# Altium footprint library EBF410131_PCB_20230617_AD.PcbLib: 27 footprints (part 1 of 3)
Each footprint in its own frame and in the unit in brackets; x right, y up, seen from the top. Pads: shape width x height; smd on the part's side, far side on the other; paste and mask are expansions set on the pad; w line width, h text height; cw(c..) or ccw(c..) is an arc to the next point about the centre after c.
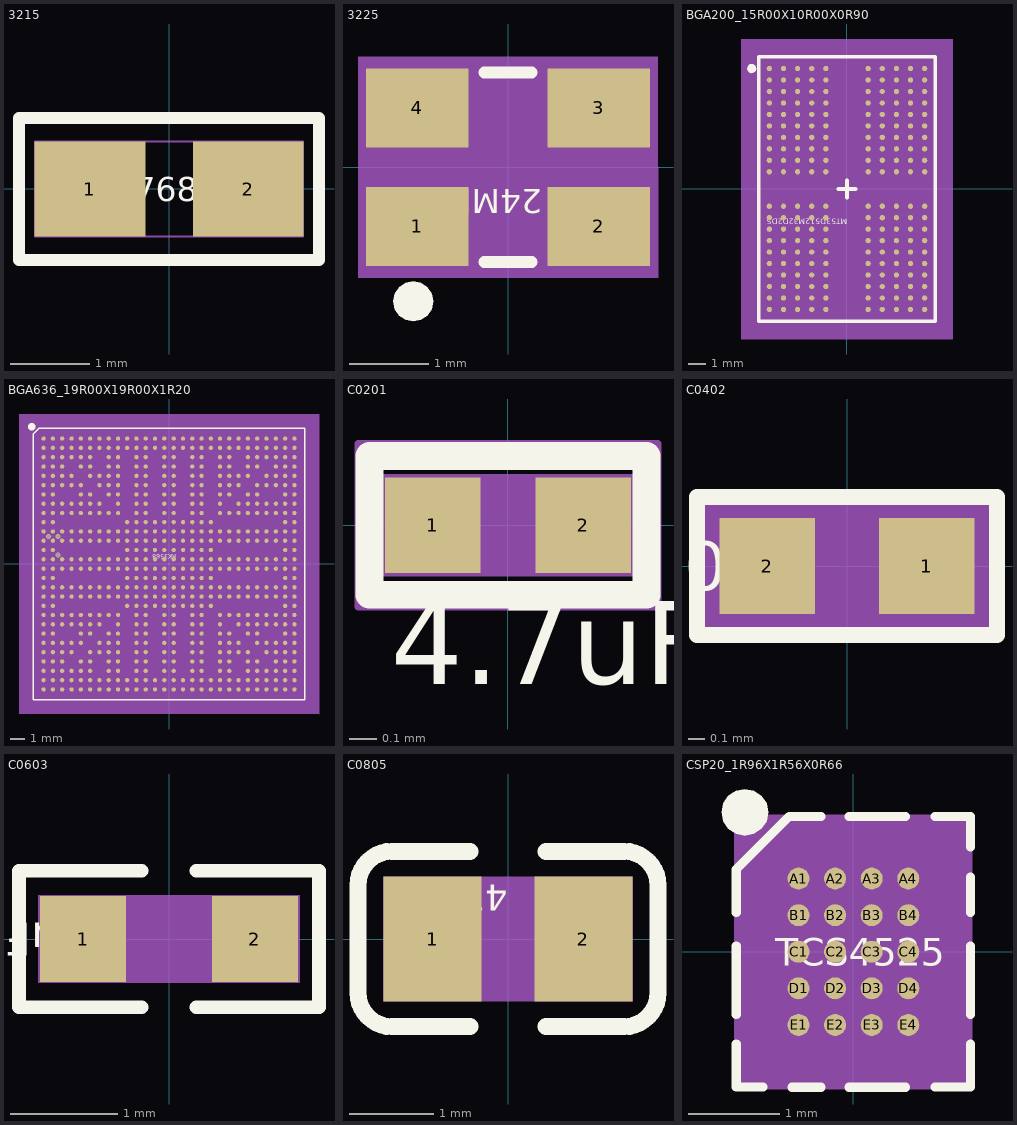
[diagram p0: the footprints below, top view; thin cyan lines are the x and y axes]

## 3215 [mm] "3215"
pads (2):
  rect 1.4x1.2 smd: 1(-1.001,0) 2(1.001,0)
Top Overlay:
  lines w0.15: -1.9,-0.899 -1.9,0.899 1.9,0.899 1.9,-0.899 -1.9,-0.899
  text "32.768KHz" at -1.097,-0.152 h0.3
Top 3D Body:
  lines w0.025: -1.699,-0.599 1.699,-0.599 1.699,0.599 -1.699,0.599 -1.699,-0.599
Mechanical 12:
  text "1" at -1.153,0 h0.38
  text "2" at 0.848,0 h0.38

## 3225 [mm] "3225"
pads (4):
  rect 1.3x1 smd: 1(-1.15,-0.75) 2(1.15,-0.75) 3(1.15,0.75) 4(-1.15,0.75)
Top Overlay:
  dashed: -1.38,-1.52 -1.436,-1.602 -1.455,-1.7 -1.436,-1.798 -1.38,-1.88 -1.298,-1.936 -1.265,-1.942 -1.2,-1.955 -1.102,-1.936 -1.02,-1.88 -0.965,-1.798 -0.945,-1.7 -0.958,-1.635 -0.965,-1.602 -1.02,-1.52 -1.102,-1.464 -1.2,-1.445 -1.298,-1.464
  lines w0.15: -0.3,-1.2 0.3,-1.2 ; -0.3,1.2 0.3,1.2
  text "24MHz" at 0.431,-0.279 h0.3
Top 3D Body:
  region: -1.9,1.4 -1.9,-1.4 1.9,-1.4 1.9,1.4
Mechanical 12:
  text "2" at 1.401,-1.001 h0.89
  text "4" at -0.899,0.499 h0.89
  text "1" at -0.899,-1.001 h0.89
  text "3" at 1.401,0.499 h0.89
Top Assembly:
  lines w0.15: -1.6,-1.25 1.6,-1.25 1.6,1.25 -1.6,1.25 -1.6,-1.25
3D body: height 3.81, standoff 0, extent -1.9,-1.4 1.9,1.4

## BGA200_15R00X10R00X0R90 [mm] "BGA200_15R00X10R00X0R90"
pads (200):
  round 0.3 smd: A1(-4.4,6.825) A2(-3.6,6.825) A3(-2.8,6.825) A4(-2,6.825) A5(-1.2,6.825) A8(1.2,6.825) A9(2,6.825) A10(2.8,6.825) A11(3.6,6.825) A12(4.4,6.825) AA1(-4.4,-6.175) AA2(-3.6,-6.175) AA3(-2.8,-6.175) AA4(-2,-6.175) AA5(-1.2,-6.175) AA8(1.2,-6.175) AA9(2,-6.175) AA10(2.8,-6.175) AA11(3.6,-6.175) AA12(4.4,-6.175) AB1(-4.4,-6.825) AB2(-3.6,-6.825) AB3(-2.8,-6.825) AB4(-2,-6.825) AB5(-1.2,-6.825) AB8(1.2,-6.825) AB9(2,-6.825) AB10(2.8,-6.825) AB11(3.6,-6.825) AB12(4.4,-6.825) B1(-4.4,6.175) B2(-3.6,6.175) B3(-2.8,6.175) B4(-2,6.175) B5(-1.2,6.175) B8(1.2,6.175) B9(2,6.175) B10(2.8,6.175) B11(3.6,6.175) B12(4.4,6.175) C1(-4.4,5.525) C2(-3.6,5.525) C3(-2.8,5.525) C4(-2,5.525) C5(-1.2,5.525) C8(1.2,5.525) C9(2,5.525) C10(2.8,5.525) C11(3.6,5.525) C12(4.4,5.525) D1(-4.4,4.875) D2(-3.6,4.875) D3(-2.8,4.875) D4(-2,4.875) D5(-1.2,4.875) D8(1.2,4.875) D9(2,4.875) D10(2.8,4.875) D11(3.6,4.875) D12(4.4,4.875) E1(-4.4,4.225) E2(-3.6,4.225) E3(-2.8,4.225) E4(-2,4.225) E5(-1.2,4.225) E8(1.2,4.225) E9(2,4.225) E10(2.8,4.225) E11(3.6,4.225) E12(4.4,4.225) F1(-4.4,3.575) F2(-3.6,3.575) F3(-2.8,3.575) F4(-2,3.575) F5(-1.2,3.575) F8(1.2,3.575) F9(2,3.575) F10(2.8,3.575) F11(3.6,3.575) F12(4.4,3.575) G1(-4.4,2.925) G2(-3.6,2.925) G3(-2.8,2.925) G4(-2,2.925) G5(-1.2,2.925) G8(1.2,2.925) G9(2,2.925) G10(2.8,2.925) G11(3.6,2.925) G12(4.4,2.925) H1(-4.4,2.275) H2(-3.6,2.275) H3(-2.8,2.275) H4(-2,2.275) H5(-1.2,2.275) H8(1.2,2.275) H9(2,2.275) H10(2.8,2.275) H11(3.6,2.275) H12(4.4,2.275) J1(-4.4,1.625) J2(-3.6,1.625) J3(-2.8,1.625) J4(-2,1.625) J5(-1.2,1.625) J8(1.2,1.625) J9(2,1.625) J10(2.8,1.625) J11(3.6,1.625) J12(4.4,1.625) K1(-4.4,0.975) K2(-3.6,0.975) K3(-2.8,0.975) K4(-2,0.975) K5(-1.2,0.975) K8(1.2,0.975) K9(2,0.975) K10(2.8,0.975) K11(3.6,0.975) K12(4.4,0.975) N1(-4.4,-0.975) N2(-3.6,-0.975) N3(-2.8,-0.975) N4(-2,-0.975) N5(-1.2,-0.975) N8(1.2,-0.975) N9(2,-0.975) N10(2.8,-0.975) N11(3.6,-0.975) N12(4.4,-0.975) P1(-4.4,-1.625) P2(-3.6,-1.625) P3(-2.8,-1.625) P4(-2,-1.625) P5(-1.2,-1.625) P8(1.2,-1.625) P9(2,-1.625) P10(2.8,-1.625) P11(3.6,-1.625) P12(4.4,-1.625) R1(-4.4,-2.275) R2(-3.6,-2.275) R3(-2.8,-2.275) R4(-2,-2.275) R5(-1.2,-2.275) R8(1.2,-2.275) R9(2,-2.275) R10(2.8,-2.275) R11(3.6,-2.275) R12(4.4,-2.275) T1(-4.4,-2.925) T2(-3.6,-2.925) T3(-2.8,-2.925) T4(-2,-2.925) T5(-1.2,-2.925) T8(1.2,-2.925) T9(2,-2.925) T10(2.8,-2.925) T11(3.6,-2.925) T12(4.4,-2.925) U1(-4.4,-3.575) U2(-3.6,-3.575) U3(-2.8,-3.575) U4(-2,-3.575) U5(-1.2,-3.575) U8(1.2,-3.575) U9(2,-3.575) U10(2.8,-3.575) U11(3.6,-3.575) U12(4.4,-3.575) V1(-4.4,-4.225) V2(-3.6,-4.225) V3(-2.8,-4.225) V4(-2,-4.225) V5(-1.2,-4.225) V8(1.2,-4.225) V9(2,-4.225) V10(2.8,-4.225) V11(3.6,-4.225) V12(4.4,-4.225) W1(-4.4,-4.875) W2(-3.6,-4.875) W3(-2.8,-4.875) W4(-2,-4.875) W5(-1.2,-4.875) W8(1.2,-4.875) W9(2,-4.875) W10(2.8,-4.875) W11(3.6,-4.875) W12(4.4,-4.875) Y1(-4.4,-5.525) Y2(-3.6,-5.525) Y3(-2.8,-5.525) Y4(-2,-5.525) Y5(-1.2,-5.525) Y8(1.2,-5.525) Y9(2,-5.525) Y10(2.8,-5.525) Y11(3.6,-5.525) Y12(4.4,-5.525)
Top Overlay:
  dashed: -5.4,7.08 -5.498,7.06 -5.58,7.005 -5.635,6.923 -5.655,6.825 -5.635,6.727 -5.617,6.7 -5.58,6.645 -5.498,6.589 -5.4,6.57 -5.302,6.589 -5.22,6.645 -5.183,6.7 -5.164,6.727 -5.145,6.825 -5.164,6.923 -5.22,7.005 -5.302,7.06
  lines w0.2: -0.5,0 0,0 ; 0,-0.5 0,0 ; 0,0.5 0,0 ; 0.5,0 0,0 ; -5,-7.5 -5,7.5 5,7.5 5,-7.5 -5,-7.5
  text "MT53D512M32D2DS" at 0,-1.676 h0.3
Top 3D Body:
  region: -6,-8.5 -6,8.5 6,8.5 6,-8.5
Mechanical 12:
  text "K8" at 1.2,0.65 h0.41
  text "N8" at 1.2,-1.3 h0.41
  text "K5" at -1.2,0.65 h0.41
  text "N5" at -1.2,-1.3 h0.41
  text "G11" at 3.6,2.437 h0.41
  text "A1" at -4.4,6.5 h0.41
  text "AB2" at -3.6,-7.313 h0.41
  text "AB11" at 3.6,-7.475 h0.41
  text "AB12" at 4.4,-7.475 h0.41
  text "A2" at -3.6,6.5 h0.41
  text "A11" at 3.6,6.337 h0.41
  text "A12" at 4.4,6.337 h0.41
  text "B1" at -4.4,5.85 h0.41
  text "B12" at 4.4,5.687 h0.41
  text "AA1" at -4.4,-6.663 h0.41
  text "AA12" at 4.4,-6.825 h0.41
  text "AB1" at -4.4,-7.313 h0.41
  text "F10" at 2.8,3.087 h0.41
  text "AA3" at -2.8,-6.663 h0.41
  text "U10" at 2.8,-4.063 h0.41
  text "AA8" at 1.2,-6.663 h0.41
  text "W8" at 1.2,-5.2 h0.41
  text "AA10" at 2.8,-6.825 h0.41
  text "AA5" at -1.2,-6.663 h0.41
  text "D8" at 1.2,4.55 h0.41
  text "B10" at 2.8,5.687 h0.41
  text "B5" at -1.2,5.85 h0.41
  text "B8" at 1.2,5.85 h0.41
  text "B3" at -2.8,5.85 h0.41
  text "D1" at -4.4,4.55 h0.41
  text "D5" at -1.2,4.55 h0.41
  text "F3" at -2.8,3.25 h0.41
  text "U3" at -2.8,-3.9 h0.41
  text "W1" at -4.4,-5.2 h0.41
  text "W5" at -1.2,-5.2 h0.41
  text "W12" at 4.4,-5.363 h0.41
  text "D12" at 4.4,4.387 h0.41
  text "B2" at -3.6,5.85 h0.41
  text "C2" at -3.6,5.2 h0.41
  text "E2" at -3.6,3.9 h0.41
  text "F2" at -3.6,3.25 h0.41
  text "F4" at -2,3.25 h0.41
  text "E4" at -2,3.9 h0.41
  text "C4" at -2,5.2 h0.41
  text "B4" at -2,5.85 h0.41
  text "C3" at -2.8,5.2 h0.41
  text "D3" at -2.8,4.55 h0.41
  text "E3" at -2.8,3.9 h0.41
  text "B11" at 3.6,5.687 h0.41
  text "C11" at 3.6,5.037 h0.41
  text "E11" at 3.6,3.737 h0.41
  text "F11" at 3.6,3.087 h0.41
  text "F9" at 2,3.25 h0.41
  text "E9" at 2,3.9 h0.41
  text "C9" at 2,5.2 h0.41
  text "B9" at 2,5.85 h0.41
  text "C10" at 2.8,5.037 h0.41
  text "D10" at 2.8,4.387 h0.41
  text "E10" at 2.8,3.737 h0.41
  text "AA2" at -3.6,-6.663 h0.41
  text "Y2" at -3.6,-5.85 h0.41
  text "V2" at -3.6,-4.55 h0.41
  text "U2" at -3.6,-3.9 h0.41
  text "U4" at -2,-3.9 h0.41
  text "V4" at -2,-4.55 h0.41
  text "Y4" at -2,-5.85 h0.41
  text "AA4" at -2,-6.663 h0.41
  text "A5" at -1.2,6.5 h0.41
  text "Y3" at -2.8,-5.85 h0.41
  text "A8" at 1.2,6.5 h0.41
  text "W3" at -2.8,-5.2 h0.41
  text "V3" at -2.8,-4.55 h0.41
  text "U12" at 4.4,-4.063 h0.41
  text "T4" at -2,-3.25 h0.41
  text "U1" at -4.4,-3.9 h0.41
  text "T9" at 2,-3.25 h0.41
  text "F12" at 4.4,3.087 h0.41
  text "G9" at 2,2.6 h0.41
  text "G4" at -2,2.6 h0.41
  text "F1" at -4.4,3.25 h0.41
  text "AA11" at 3.6,-6.825 h0.41
  text "Y11" at 3.6,-6.013 h0.41
  text "V11" at 3.6,-4.713 h0.41
  text "U11" at 3.6,-4.063 h0.41
  text "U9" at 2,-3.9 h0.41
  text "V9" at 2,-4.55 h0.41
  text "Y9" at 2,-5.85 h0.41
  text "AA9" at 2,-6.663 h0.41
  text "Y10" at 2.8,-6.013 h0.41
  text "W10" at 2.8,-5.363 h0.41
  text "V10" at 2.8,-4.713 h0.41
  text "P8" at 1.2,-1.95 h0.41
  text "J2" at -3.6,1.3 h0.41
  text "J5" at -1.2,1.3 h0.41
  text "R10" at 2.8,-2.763 h0.41
  text "P11" at 3.6,-2.113 h0.41
  text "P2" at -3.6,-1.95 h0.41
  text "T2" at -3.6,-3.25 h0.41
  text "G2" at -3.6,2.6 h0.41
  text "P9" at 2,-1.95 h0.41
  text "P4" at -2,-1.95 h0.41
  text "H2" at -3.6,1.95 h0.41
  text "H10" at 2.8,1.787 h0.41
  text "R2" at -3.6,-2.6 h0.41
  text "H11" at 3.6,1.787 h0.41
  text "H9" at 2,1.95 h0.41
  text "G12" at 4.4,2.437 h0.41
  text "P3" at -2.8,-1.95 h0.41
  text "N2" at -3.6,-1.3 h0.41
  text "G8" at 1.2,2.6 h0.41
  text "C8" at 1.2,5.2 h0.41
  text "E12" at 4.4,3.737 h0.41
  text "V12" at 4.4,-4.713 h0.41
  text "N4" at -2,-1.3 h0.41
  text "C5" at -1.2,5.2 h0.41
  text "D4" at -2,4.55 h0.41
  text "K2" at -3.6,0.65 h0.41
  text "AB10" at 2.8,-7.475 h0.41
  text "AB3" at -2.8,-7.313 h0.41
  text "D11" at 3.6,4.387 h0.41
  text "A10" at 2.8,6.337 h0.41
  text "A3" at -2.8,6.5 h0.41
  text "C1" at -4.4,5.2 h0.41
  text "D2" at -3.6,4.55 h0.41
  text "G3" at -2.8,2.6 h0.41
  text "E1" at -4.4,3.9 h0.41
  text "G1" at -4.4,2.6 h0.41
  text "J1" at -4.4,1.3 h0.41
  text "G5" at -1.2,2.6 h0.41
  text "D9" at 2,4.55 h0.41
  text "E8" at 1.2,3.9 h0.41
  text "G10" at 2.8,2.437 h0.41
  text "T12" at 4.4,-3.413 h0.41
  text "Y12" at 4.4,-6.013 h0.41
  text "W11" at 3.6,-5.363 h0.41
  text "T10" at 2.8,-3.413 h0.41
  text "T8" at 1.2,-3.25 h0.41
  text "V8" at 1.2,-4.55 h0.41
  text "AB8" at 1.2,-7.313 h0.41
  text "T5" at -1.2,-3.25 h0.41
  text "P1" at -4.4,-1.95 h0.41
  text "T1" at -4.4,-3.25 h0.41
  text "V1" at -4.4,-4.55 h0.41
  text "W2" at -3.6,-5.2 h0.41
  text "Y1" at -4.4,-5.85 h0.41
  text "V5" at -1.2,-4.55 h0.41
  text "T3" at -2.8,-3.25 h0.41
  text "J12" at 4.4,1.137 h0.41
  text "K11" at 3.6,0.487 h0.41
  text "P12" at 4.4,-2.113 h0.41
  text "N11" at 3.6,-1.463 h0.41
  text "W9" at 2,-5.2 h0.41
  text "AB5" at -1.2,-7.313 h0.41
  text "J3" at -2.8,1.3 h0.41
  text "J10" at 2.8,1.137 h0.41
  text "K4" at -2,0.65 h0.41
  text "P10" at 2.8,-2.113 h0.41
  text "Y8" at 1.2,-5.85 h0.41
  text "K9" at 2,0.65 h0.41
  text "N9" at 2,-1.3 h0.41
  text "Y5" at -1.2,-5.85 h0.41
  text "W4" at -2,-5.2 h0.41
  text "E5" at -1.2,3.9 h0.41
  text "C12" at 4.4,5.037 h0.41
  text "J11" at 3.6,1.137 h0.41
  text "P5" at -1.2,-1.95 h0.41
  text "R9" at 2,-2.6 h0.41
  text "R11" at 3.6,-2.763 h0.41
  text "J4" at -2,1.3 h0.41
  text "J8" at 1.2,1.3 h0.41
  text "J9" at 2,1.3 h0.41
  text "H4" at -2,1.95 h0.41
  text "H3" at -2.8,1.95 h0.41
  text "R3" at -2.8,-2.6 h0.41
  text "R4" at -2,-2.6 h0.41
  text "T11" at 3.6,-3.413 h0.41
  text "A9" at 2,6.5 h0.41
  text "A4" at -2,6.5 h0.41
  text "H1" at -4.4,1.95 h0.41
  text "H8" at 1.2,1.95 h0.41
  text "N1" at -4.4,-1.3 h0.41
  text "R1" at -4.4,-2.6 h0.41
  text "U5" at -1.2,-3.9 h0.41
  text "K12" at 4.4,0.487 h0.41
  text "H12" at 4.4,1.787 h0.41
  text "N12" at 4.4,-1.463 h0.41
  text "R12" at 4.4,-2.763 h0.41
  text "R8" at 1.2,-2.6 h0.41
  text "U8" at 1.2,-3.9 h0.41
  text "AB9" at 2,-7.313 h0.41
  text "N10" at 2.8,-1.463 h0.41
  text "K10" at 2.8,0.487 h0.41
  text "N3" at -2.8,-1.3 h0.41
  text "K3" at -2.8,0.65 h0.41
  text "F8" at 1.2,3.25 h0.41
  text "F5" at -1.2,3.25 h0.41
  text "H5" at -1.2,1.95 h0.41
  text "K1" at -4.4,0.65 h0.41
  text "R5" at -1.2,-2.6 h0.41
  text "AB4" at -2,-7.313 h0.41
Top Assembly:
  dashed: -5.08,7.62 -5.08,-7.62 5.08,-7.62 5.08,7.62
3D body: height 3.81, standoff 0, extent -6,-8.5 6,8.5

## BGA636_19R00X19R00X1R20 [mm] "BGA636_19R00X19R00X1R20"
pads (636):
  round 0.3 smd: A1(-8.78,8.78) A2(-8.13,8.78) A3(-7.48,8.78) A4(-6.82,8.78) A5(-6.17,8.78) A6(-5.52,8.78) A7(-4.87,8.78) A8(-4.22,8.78) A9(-3.57,8.78) A10(-2.93,8.78) A11(-2.28,8.78) A12(-1.63,8.78) A13(-0.98,8.78) A14(-0.33,8.78) A15(0.33,8.78) A16(0.98,8.78) A17(1.63,8.78) A18(2.28,8.78) A19(2.93,8.78) A20(3.57,8.78) A21(4.22,8.78) A22(4.87,8.78) A23(5.52,8.78) A24(6.17,8.78) A25(6.82,8.78) A26(7.48,8.78) A27(8.13,8.78) A28(8.78,8.78) AA1(-8.78,-4.22) AA2(-8.13,-4.22) AA3(-7.48,-4.22) AA4(-6.82,-4.22) AA5(-6.17,-4.22) AA6(-5.52,-4.22) AA7(-4.87,-4.22) AA9(-3.57,-4.22) AA11(-2.28,-4.22) AA12(-1.63,-4.22) AA14(-0.33,-4.22) AA15(0.33,-4.22) AA17(1.63,-4.22) AA18(2.28,-4.22) AA20(3.57,-4.22) AA22(4.87,-4.22) AA23(5.52,-4.22) AA24(6.17,-4.22) AA25(6.82,-4.22) AA26(7.48,-4.22) AA27(8.13,-4.22) AA28(8.78,-4.22) AB1(-8.78,-4.87) AB2(-8.13,-4.87) AB5(-6.17,-4.87) AB6(-5.52,-4.87) AB8(-4.22,-4.87) AB9(-3.57,-4.87) AB11(-2.28,-4.87) AB12(-1.63,-4.87) AB14(-0.33,-4.87) AB15(0.33,-4.87) AB17(1.63,-4.87) AB18(2.28,-4.87) AB20(3.57,-4.87) AB21(4.22,-4.87) AB23(5.52,-4.87) AB24(6.17,-4.87) AB27(8.13,-4.87) AB28(8.78,-4.87) AC1(-8.78,-5.52) AC2(-8.13,-5.52) AC3(-7.48,-5.52) AC4(-6.82,-5.52) AC5(-6.17,-5.52) AC7(-4.87,-5.52) AC8(-4.22,-5.52) AC9(-3.57,-5.52) AC11(-2.28,-5.52) AC12(-1.63,-5.52) AC14(-0.33,-5.52) AC15(0.33,-5.52) AC17(1.63,-5.52) AC18(2.28,-5.52) AC20(3.57,-5.52) AC21(4.22,-5.52) AC22(4.87,-5.52) AC24(6.17,-5.52) AC25(6.82,-5.52) AC26(7.48,-5.52) AC27(8.13,-5.52) AC28(8.78,-5.52) AD1(-8.78,-6.17) AD2(-8.13,-6.17) AD3(-7.48,-6.17) AD4(-6.82,-6.17) AD6(-5.52,-6.17) AD7(-4.87,-6.17) AD8(-4.22,-6.17) AD9(-3.57,-6.17) AD11(-2.28,-6.17) AD12(-1.63,-6.17) AD14(-0.33,-6.17) AD15(0.33,-6.17) AD17(1.63,-6.17) AD18(2.28,-6.17) AD20(3.57,-6.17) AD21(4.22,-6.17) AD22(4.87,-6.17) AD23(5.52,-6.17) AD25(6.82,-6.17) AD26(7.48,-6.17) AD27(8.13,-6.17) AD28(8.78,-6.17) AE1(-8.78,-6.82) AE2(-8.13,-6.82) AE3(-7.48,-6.82) AE5(-6.17,-6.82) AE6(-5.52,-6.82) AE8(-4.22,-6.82) AE9(-3.57,-6.82) AE11(-2.28,-6.82) AE12(-1.63,-6.82) AE14(-0.33,-6.82) AE15(0.33,-6.82) AE17(1.63,-6.82) AE18(2.28,-6.82) AE20(3.57,-6.82) AE21(4.22,-6.82) AE23(5.52,-6.82) AE24(6.17,-6.82) AE26(7.48,-6.82) AE27(8.13,-6.82) AE28(8.78,-6.82) AF1(-8.78,-7.48) AF2(-8.13,-7.48) AF3(-7.48,-7.48) AF4(-6.82,-7.48) AF5(-6.17,-7.48) AF6(-5.52,-7.48) AF8(-4.22,-7.48) AF9(-3.57,-7.48) AF11(-2.28,-7.48) AF12(-1.63,-7.48) AF14(-0.33,-7.48) AF15(0.33,-7.48) AF17(1.63,-7.48) AF18(2.28,-7.48) AF20(3.57,-7.48) AF21(4.22,-7.48) AF23(5.52,-7.48) AF24(6.17,-7.48) AF25(6.82,-7.48) AF26(7.48,-7.48) AF27(8.13,-7.48) AF28(8.78,-7.48) AG1(-8.78,-8.13) AG2(-8.13,-8.13) AG3(-7.48,-8.13) AG4(-6.82,-8.13) AG5(-6.17,-8.13) AG6(-5.52,-8.13) AG7(-4.87,-8.13) AG8(-4.22,-8.13) AG9(-3.57,-8.13) AG10(-2.93,-8.13) AG11(-2.28,-8.13) AG12(-1.63,-8.13) AG13(-0.98,-8.13) AG14(-0.33,-8.13) AG15(0.33,-8.13) AG16(0.98,-8.13) AG17(1.63,-8.13) AG18(2.28,-8.13) AG19(2.93,-8.13) AG20(3.57,-8.13) AG21(4.22,-8.13) AG22(4.87,-8.13) AG23(5.52,-8.13) AG24(6.17,-8.13) AG25(6.82,-8.13) AG26(7.48,-8.13) AG27(8.13,-8.13) AG28(8.78,-8.13) AH1(-8.78,-8.78) AH2(-8.13,-8.78) AH3(-7.48,-8.78) AH4(-6.82,-8.78) AH5(-6.17,-8.78) AH6(-5.52,-8.78) AH7(-4.87,-8.78) AH8(-4.22,-8.78) AH9(-3.57,-8.78) AH10(-2.93,-8.78) AH11(-2.28,-8.78) AH12(-1.63,-8.78) AH13(-0.98,-8.78) AH14(-0.33,-8.78) AH15(0.33,-8.78) AH16(0.98,-8.78) AH17(1.63,-8.78) AH18(2.28,-8.78) AH19(2.93,-8.78) AH20(3.57,-8.78) AH21(4.22,-8.78) AH22(4.87,-8.78) AH23(5.52,-8.78) AH24(6.17,-8.78) AH25(6.82,-8.78) AH26(7.48,-8.78) AH27(8.13,-8.78) AH28(8.78,-8.78) B1(-8.78,8.13) B2(-8.13,8.13) B3(-7.48,8.13) B4(-6.82,8.13) B5(-6.17,8.13) B6(-5.52,8.13) B7(-4.87,8.13) B8(-4.22,8.13) B9(-3.57,8.13) B10(-2.93,8.13) B11(-2.28,8.13) B12(-1.63,8.13) B13(-0.98,8.13) B14(-0.33,8.13) B15(0.33,8.13) B16(0.98,8.13) B17(1.63,8.13) B18(2.28,8.13) B19(2.93,8.13) B20(3.57,8.13) B21(4.22,8.13) B22(4.87,8.13) B23(5.52,8.13) B24(6.17,8.13) B25(6.82,8.13) B26(7.48,8.13) B27(8.13,8.13) B28(8.78,8.13) C1(-8.78,7.48) C2(-8.13,7.48) C3(-7.48,7.48) C4(-6.82,7.48) C5(-6.17,7.48) C6(-5.52,7.48) C8(-4.22,7.48) C9(-3.57,7.48) C11(-2.28,7.48) C12(-1.63,7.48) C14(-0.33,7.48) C15(0.33,7.48) C17(1.63,7.48) C18(2.28,7.48) C20(3.57,7.48) C21(4.22,7.48) C23(5.52,7.48) C24(6.17,7.48) C25(6.82,7.48) C26(7.48,7.48) C27(8.13,7.48) C28(8.78,7.48) D1(-8.78,6.82) D2(-8.13,6.82) D3(-7.48,6.82) D5(-6.17,6.82) D6(-5.52,6.82) D8(-4.22,6.82) D9(-3.57,6.82) D11(-2.28,6.82) D12(-1.63,6.82) D14(-0.33,6.82) D15(0.33,6.82) D17(1.63,6.82) D18(2.28,6.82) D20(3.57,6.82) D21(4.22,6.82) D23(5.52,6.82) D24(6.17,6.82) D26(7.48,6.82) D27(8.13,6.82) D28(8.78,6.82) E1(-8.78,6.17) E2(-8.13,6.17) E3(-7.48,6.17) E4(-6.82,6.17) E6(-5.52,6.17) E7(-4.87,6.17) E8(-4.22,6.17) E9(-3.57,6.17) E11(-2.28,6.17) E12(-1.63,6.17) E14(-0.33,6.17) E15(0.33,6.17) E17(1.63,6.17) E18(2.28,6.17) E20(3.57,6.17) E21(4.22,6.17) E22(4.87,6.17) E23(5.52,6.17) E25(6.82,6.17) E26(7.48,6.17) E27(8.13,6.17) E28(8.78,6.17) F1(-8.78,5.52) F2(-8.13,5.52) F3(-7.48,5.52) F4(-6.82,5.52) F5(-6.17,5.52) F7(-4.87,5.52) F8(-4.22,5.52) F9(-3.57,5.52) F11(-2.28,5.52) F12(-1.63,5.52) F14(-0.33,5.52) F15(0.33,5.52) F17(1.63,5.52) F18(2.28,5.52) F20(3.57,5.52) F21(4.22,5.52) F22(4.87,5.52) F24(6.17,5.52) F25(6.82,5.52) F26(7.48,5.52) F27(8.13,5.52) F28(8.78,5.52) G1(-8.78,4.87) G2(-8.13,4.87) G5(-6.17,4.87) G6(-5.52,4.87) G8(-4.22,4.87) G9(-3.57,4.87) G11(-2.28,4.87) G12(-1.63,4.87) G14(-0.33,4.87) G15(0.33,4.87) G17(1.63,4.87) G18(2.28,4.87) G20(3.57,4.87) G21(4.22,4.87) G23(5.52,4.87) G24(6.17,4.87) G27(8.13,4.87) G28(8.78,4.87) H1(-8.78,4.22) H2(-8.13,4.22) H3(-7.48,4.22) H4(-6.82,4.22) H5(-6.17,4.22) H6(-5.52,4.22) H7(-4.87,4.22) H9(-3.57,4.22) H11(-2.28,4.22) H12(-1.63,4.22) H14(-0.33,4.22) H15(0.33,4.22) H17(1.63,4.22) H18(2.28,4.22) H20(3.57,4.22) H22(4.87,4.22) H23(5.52,4.22) H24(6.17,4.22) H25(6.82,4.22) H26(7.48,4.22) H27(8.13,4.22) H28(8.78,4.22) J1(-8.78,3.57) J2(-8.13,3.57) J3(-7.48,3.57) J4(-6.82,3.57) J5(-6.17,3.57) J6(-5.52,3.57) J7(-4.87,3.57) J8(-4.22,3.57) J9(-3.57,3.57) J11(-2.28,3.57) J12(-1.63,3.57) J14(-0.33,3.57) J15(0.33,3.57) J17(1.63,3.57) J18(2.28,3.57) J20(3.57,3.57) J21(4.22,3.57) J22(4.87,3.57) J23(5.52,3.57) J24(6.17,3.57) J25(6.82,3.57) J26(7.48,3.57) J27(8.13,3.57) J28(8.78,3.57) K1(-8.78,2.93) K2(-8.13,2.93) K10(-2.93,2.93) K11(-2.28,2.93) K12(-1.63,2.93) K13(-0.98,2.93) K14(-0.33,2.93) K15(0.33,2.93) K16(0.98,2.93) K17(1.63,2.93) K18(2.28,2.93) K19(2.93,2.93) K27(8.13,2.93) K28(8.78,2.93) L1(-8.78,2.28) L2(-8.13,2.28) L3(-7.48,2.28) L4(-6.82,2.28) L5(-6.17,2.28) L6(-5.52,2.28) L7(-4.87,2.28) L8(-4.22,2.28) L9(-3.57,2.28) L10(-2.93,2.28) L11(-2.28,2.28) L12(-1.63,2.28) L13(-0.98,2.28) L14(-0.33,2.28) L15(0.33,2.28) L16(0.98,2.28) L17(1.63,2.28) L18(2.28,2.28) L19(2.93,2.28) L20(3.57,2.28) L21(4.22,2.28) L22(4.87,2.28) L23(5.52,2.28) L24(6.17,2.28) L25(6.82,2.28) L26(7.48,2.28) L27(8.13,2.28) L28(8.78,2.28) M1(-8.78,1.63) M2(-8.13,1.63) M3(-7.48,1.63) M4(-6.82,1.63) M5(-6.17,1.63) M6(-5.52,1.63) M7(-4.87,1.63) M8(-4.22,1.63) M9(-3.57,1.63) M10(-2.93,1.63) M11(-2.28,1.63) M12(-1.63,1.63) M13(-0.98,1.63) M14(-0.33,1.63) M15(0.33,1.63) M16(0.98,1.63) M17(1.63,1.63) M18(2.28,1.63) M19(2.93,1.63) M20(3.57,1.63) M21(4.22,1.63) M22(4.87,1.63) M23(5.52,1.63) M24(6.17,1.63) M25(6.82,1.63) M26(7.48,1.63) M27(8.13,1.63) M28(8.78,1.63) N1(-8.78,0.98) N2(-8.13,0.98) N10(-2.93,0.98) N11(-2.28,0.98) N12(-1.63,0.98) N13(-0.98,0.98) N14(-0.33,0.98) N15(0.33,0.98) N16(0.98,0.98) N17(1.63,0.98) N18(2.28,0.98) N19(2.93,0.98) N27(8.13,0.98) N28(8.78,0.98) P1(-8.78,0.33) P2(-8.13,0.33) P3(-7.48,0.33) P4(-6.82,0.33) P5(-6.17,0.33) P6(-5.52,0.33) P7(-4.87,0.33) P8(-4.22,0.33) P9(-3.57,0.33) P10(-2.93,0.33) P11(-2.28,0.33) P12(-1.63,0.33) P13(-0.98,0.33) P14(-0.33,0.33) P15(0.33,0.33) P16(0.98,0.33) P17(1.63,0.33) P18(2.28,0.33) P19(2.93,0.33) P20(3.57,0.33) P21(4.22,0.33) P22(4.87,0.33) P23(5.52,0.33) P24(6.17,0.33) P25(6.82,0.33) P26(7.48,0.33) P27(8.13,0.33) P28(8.78,0.33) R1(-8.78,-0.33) R2(-8.13,-0.33) R3(-7.48,-0.33) R4(-6.82,-0.33) R5(-6.17,-0.33) R6(-5.52,-0.33) R7(-4.87,-0.33) R8(-4.22,-0.33) R9(-3.57,-0.33) R10(-2.93,-0.33) R11(-2.28,-0.33) R12(-1.63,-0.33) R13(-0.98,-0.33) R14(-0.33,-0.33) R15(0.33,-0.33) R16(0.98,-0.33) R17(1.63,-0.33) R18(2.28,-0.33) R19(2.93,-0.33) R20(3.57,-0.33) R21(4.22,-0.33) R22(4.87,-0.33) R23(5.52,-0.33) R24(6.17,-0.33) R25(6.82,-0.33) R26(7.48,-0.33) R27(8.13,-0.33) R28(8.78,-0.33) T1(-8.78,-0.98) T2(-8.13,-0.98) T10(-2.93,-0.98) T11(-2.28,-0.98) T12(-1.63,-0.98) T13(-0.98,-0.98) T14(-0.33,-0.98) T15(0.33,-0.98) T16(0.98,-0.98) T17(1.63,-0.98) T18(2.28,-0.98) T19(2.93,-0.98) T27(8.13,-0.98) T28(8.78,-0.98) U1(-8.78,-1.63) U2(-8.13,-1.63) U3(-7.48,-1.63) U4(-6.82,-1.63) U5(-6.17,-1.63) U6(-5.52,-1.63) U7(-4.87,-1.63) U8(-4.22,-1.63) U9(-3.57,-1.63) U10(-2.93,-1.63) U11(-2.28,-1.63) U12(-1.63,-1.63) U13(-0.98,-1.63) U14(-0.33,-1.63) U15(0.33,-1.63) U16(0.98,-1.63) U17(1.63,-1.63) U18(2.28,-1.63) U19(2.93,-1.63) U20(3.57,-1.63) U21(4.22,-1.63) U22(4.87,-1.63) U23(5.52,-1.63) U24(6.17,-1.63) U25(6.82,-1.63) U26(7.48,-1.63) U27(8.13,-1.63) U28(8.78,-1.63) V1(-8.78,-2.28) V2(-8.13,-2.28) V3(-7.48,-2.28) V4(-6.82,-2.28) V5(-6.17,-2.28) V6(-5.52,-2.28) V7(-4.87,-2.28) V8(-4.22,-2.28) V9(-3.57,-2.28) V10(-2.93,-2.28) V11(-2.28,-2.28) V12(-1.63,-2.28) V13(-0.98,-2.28) V14(-0.33,-2.28) V15(0.33,-2.28) V16(0.98,-2.28) V17(1.63,-2.28) V18(2.28,-2.28) V19(2.93,-2.28) V20(3.57,-2.28) V21(4.22,-2.28) V22(4.87,-2.28) V23(5.52,-2.28) V24(6.17,-2.28) V25(6.82,-2.28) V26(7.48,-2.28) V27(8.13,-2.28) V28(8.78,-2.28) W1(-8.78,-2.93) W2(-8.13,-2.93) W10(-2.93,-2.93) W11(-2.28,-2.93) W12(-1.63,-2.93) W13(-0.98,-2.93) W14(-0.33,-2.93) W15(0.33,-2.93) W16(0.98,-2.93) W17(1.63,-2.93) W18(2.28,-2.93) W19(2.93,-2.93) W27(8.13,-2.93) W28(8.78,-2.93) Y1(-8.78,-3.57) Y2(-8.13,-3.57) Y3(-7.48,-3.57) Y4(-6.82,-3.57) Y5(-6.17,-3.57) Y6(-5.52,-3.57) Y7(-4.87,-3.57) Y8(-4.22,-3.57) Y9(-3.57,-3.57) Y11(-2.28,-3.57) Y12(-1.63,-3.57) Y14(-0.33,-3.57) Y15(0.33,-3.57) Y17(1.63,-3.57) Y18(2.28,-3.57) Y20(3.57,-3.57) Y21(4.22,-3.57) Y22(4.87,-3.57) Y23(5.52,-3.57) Y24(6.17,-3.57) Y25(6.82,-3.57) Y26(7.48,-3.57) Y27(8.13,-3.57) Y28(8.78,-3.57)
via -7.784,0.634 diameter 0.356 hole 0.203
via -8.434,1.934 diameter 0.356 hole 0.203
via -7.784,1.934 diameter 0.356 hole 0.203
Top Layer:
  lines w0.254: -7.48,0.33 -7.48,0.33
Top Overlay:
  dashed: -9.78,9.42 -9.698,9.364 -9.6,9.345 -9.502,9.364 -9.42,9.42 -9.365,9.502 -9.358,9.535 -9.345,9.6 -9.365,9.698 -9.42,9.78 -9.502,9.835 -9.6,9.855 -9.665,9.842 -9.698,9.835 -9.78,9.78 -9.836,9.698 -9.855,9.6 -9.836,9.502
  lines w0.13: -9.5,-9.5 9.5,-9.5 9.5,9.5 -9.1,9.5 -9.5,9.1 -9.5,-9.5
  text "RK3568" at 0.518,0.67 h0.3
Top 3D Body:
  region: -10.5,10.5 -10.5,-10.5 10.5,-10.5 10.5,10.5
Mechanical 12:
  text "F5" at -5.811,5.879 h0.64
  text "F8" at -3.861,5.879 h0.64
  text "F7" at -4.511,5.879 h0.64
  text "P7" at -4.511,0.689 h0.64
  text "P5" at -5.811,0.689 h0.64
  text "M4" at -6.461,1.989 h0.64
  text "M5" at -5.811,1.989 h0.64
  text "R5" at -5.811,0.029 h0.64
  text "M7" at -4.511,1.989 h0.64
  text "R7" at -4.511,0.029 h0.64
  text "P4" at -6.461,0.689 h0.64
  text "R4" at -6.461,0.029 h0.64
  text "P1" at -8.421,0.689 h0.64
  text "P2" at -7.771,0.689 h0.64
  text "P8" at -3.861,0.689 h0.64
  text "R25" at 7.359,0.209 h0.64
  text "R24" at 6.709,0.209 h0.64
  text "U24" at 6.709,-1.091 h0.64
  text "U25" at 7.359,-1.091 h0.64
  text "AB23" at 6.238,-4.152 h0.64
  text "AE26" at 8.198,-6.102 h0.64
  text "AA20" at 4.288,-3.502 h0.64
  text "AD25" at 7.538,-5.452 h0.64
  text "J14" at 0.209,4.109 h0.64
  text "K10" at -2.391,3.469 h0.64
  text "M10" at -2.391,2.169 h0.64
  text "L10" at -2.391,2.819 h0.64
  text "J12" at -1.091,4.109 h0.64
  text "J11" at -1.741,4.109 h0.64
  text "F18" at 2.819,6.059 h0.64
  text "D20" at 4.109,7.359 h0.64
  text "D24" at 6.709,7.359 h0.64
  text "P27" at 8.669,0.869 h0.64
  text "P28" at 9.319,0.869 h0.64
  text "AC20" at 4.288,-4.802 h0.64
  text "AH24" at 6.888,-8.062 h0.64
  text "F2" at -7.771,5.879 h0.64
  text "AG12" at -0.912,-7.412 h0.64
  text "C27" at 8.669,8.019 h0.64
  text "E1" at -8.421,6.529 h0.64
  text "AF5" at -5.631,-6.941 h0.64
  text "AH12" at -0.912,-8.062 h0.64
  text "E2" at -7.771,6.529 h0.64
  text "AF6" at -4.981,-6.941 h0.64
  text "AG11" at -1.562,-7.412 h0.64
  text "D1" at -8.421,7.179 h0.64
  text "AH11" at -1.562,-8.062 h0.64
  text "L23" at 6.059,2.819 h0.64
  text "J1" at -8.421,3.929 h0.64
  text "AD6" at -4.981,-5.631 h0.64
  text "AE11" at -1.562,-6.102 h0.64
  text "E27" at 8.669,6.709 h0.64
  text "J2" at -7.771,3.929 h0.64
  text "AD11" at -1.562,-5.452 h0.64
  text "E28" at 9.319,6.709 h0.64
  text "H1" at -8.421,4.579 h0.64
  text "AD9" at -3.031,-5.631 h0.64
  text "B28" at 9.319,8.669 h0.64
  text "M24" at 6.709,2.169 h0.64
  text "H4" at -6.461,4.579 h0.64
  text "AE9" at -3.031,-6.281 h0.64
  text "AG10" at -2.212,-7.412 h0.64
  text "AH10" at -2.212,-8.062 h0.64
  text "P24" at 6.709,0.869 h0.64
  text "B27" at 8.669,8.669 h0.64
  text "AG9" at -3.031,-7.591 h0.64
  text "P25" at 7.359,0.869 h0.64
  text "AH9" at -3.031,-8.241 h0.64
  text "C28" at 9.319,8.019 h0.64
  text "H5" at -5.811,4.579 h0.64
  text "Y22" at 5.409,-3.031 h0.64
  text "V6" at -5.161,-1.921 h0.64
  text "G1" at -8.421,5.229 h0.64
  text "V5" at -5.811,-1.921 h0.64
  text "G2" at -7.771,5.229 h0.64
  text "AG4" at -6.281,-7.591 h0.64
  text "D27" at 8.669,7.359 h0.64
  text "AF4" at -6.281,-6.941 h0.64
  text "AH3" at -6.941,-8.241 h0.64
  text "AF27" at 8.848,-6.762 h0.64
  text "AG3" at -6.941,-7.591 h0.64
  text "AF28" at 9.498,-6.762 h0.64
  text "D26" at 8.019,7.359 h0.64
  text "E25" at 7.359,6.709 h0.64
  text "M1" at -8.421,1.989 h0.64
  text "AH26" at 8.198,-8.062 h0.64
  text "Y27" at 8.669,-3.031 h0.64
  text "W27" at 8.669,-2.391 h0.64
  text "AD18" at 2.998,-5.452 h0.64
  text "W28" at 9.319,-2.391 h0.64
  text "AE18" at 2.998,-6.102 h0.64
  text "Y28" at 9.319,-3.031 h0.64
  text "AG1" at -8.241,-7.591 h0.64
  text "AD17" at 2.348,-5.452 h0.64
  text "N2" at -7.771,1.339 h0.64
  text "P10" at -2.391,0.869 h0.64
  text "AF2" at -7.591,-6.941 h0.64
  text "AC17" at 2.348,-4.802 h0.64
  text "L7" at -4.511,2.639 h0.64
  text "P9" at -3.211,0.689 h0.64
  text "AF1" at -8.241,-6.941 h0.64
  text "AD14" at 0.388,-5.452 h0.64
  text "L6" at -5.161,2.639 h0.64
  text "R8" at -3.861,0.029 h0.64
  text "AC14" at 0.388,-4.802 h0.64
  text "K2" at -7.771,3.289 h0.64
  text "AD12" at -0.912,-5.452 h0.64
  text "F28" at 9.319,6.059 h0.64
  text "J6" at -5.161,3.929 h0.64
  text "AE1" at -8.241,-6.281 h0.64
  text "AE12" at -0.912,-6.102 h0.64
  text "G27" at 8.669,5.409 h0.64
  text "J7" at -4.511,3.929 h0.64
  text "AD15" at 1.048,-5.452 h0.64
  text "G28" at 9.319,5.409 h0.64
  text "L4" at -6.461,2.639 h0.64
  text "M15" at 0.869,2.169 h0.64
  text "AE15" at 1.048,-6.102 h0.64
  text "J4" at -6.461,3.929 h0.64
  text "AD4" at -6.281,-5.631 h0.64
  text "AC5" at -5.631,-4.981 h0.64
  text "T28" at 9.319,-0.441 h0.64
  text "L2" at -7.771,2.639 h0.64
  text "P22" at 5.409,0.869 h0.64
  text "AA6" at -4.981,-3.681 h0.64
  text "T27" at 8.669,-0.441 h0.64
  text "L1" at -8.421,2.639 h0.64
  text "P23" at 6.059,0.869 h0.64
  text "AD2" at -7.591,-5.631 h0.64
  text "AB5" at -5.631,-4.331 h0.64
  text "R28" at 9.319,0.209 h0.64
  text "M23" at 6.059,2.169 h0.64
  text "AB1" at -8.241,-4.331 h0.64
  text "R27" at 8.669,0.209 h0.64
  text "Y7" at -4.511,-3.211 h0.64
  text "C24" at 6.709,8.019 h0.64
  text "F27" at 8.669,6.059 h0.64
  text "AC24" at 6.888,-4.802 h0.64
  text "A27" at 8.669,9.319 h0.64
  text "A23" at 6.059,9.319 h0.64
  text "D23" at 6.059,7.359 h0.64
  text "H25" at 7.359,4.759 h0.64
  text "F20" at 4.109,6.059 h0.64
  text "V28" at 9.319,-1.741 h0.64
  text "K17" at 2.169,3.469 h0.64
  text "L15" at 0.869,2.819 h0.64
  text "K15" at 0.869,3.469 h0.64
  text "J15" at 0.869,4.109 h0.64
  text "K18" at 2.819,3.469 h0.64
  text "L17" at 2.169,2.819 h0.64
  text "K16" at 1.519,3.469 h0.64
  text "L16" at 1.519,2.819 h0.64
  text "L18" at 2.819,2.819 h0.64
  text "M17" at 2.169,2.169 h0.64
  text "C23" at 6.059,8.019 h0.64
  text "J28" at 9.319,4.109 h0.64
  text "F24" at 6.709,6.059 h0.64
  text "V27" at 8.669,-1.741 h0.64
  text "U28" at 9.319,-1.091 h0.64
  text "U27" at 8.669,-1.091 h0.64
  text "B10" at -2.391,8.669 h0.64
  text "W14" at 0.209,-2.391 h0.64
  text "A9" at -3.211,9.139 h0.64
  text "Y14" at 0.209,-3.031 h0.64
  text "D12" at -1.091,7.359 h0.64
  text "AC1" at -8.241,-4.981 h0.64
  text "E12" at -1.091,6.709 h0.64
  text "AF24" at 6.888,-6.762 h0.64
  text "A12" at -1.091,9.319 h0.64
  text "AB21" at 4.938,-4.152 h0.64
  text "D15" at 0.869,7.359 h0.64
  text "E15" at 0.869,6.709 h0.64
  text "E14" at 0.209,6.709 h0.64
  text "F25" at 7.359,6.059 h0.64
  text "H24" at 6.709,4.759 h0.64
  text "A22" at 5.409,9.319 h0.64
  text "D14" at 0.209,7.359 h0.64
  text "V24" at 6.709,-1.741 h0.64
  text "V25" at 7.359,-1.741 h0.64
  text "A11" at -1.741,9.319 h0.64
  text "H23" at 6.059,4.759 h0.64
  text "B11" at -1.741,8.669 h0.64
  text "W16" at 1.519,-2.391 h0.64
  text "Y17" at 2.169,-3.031 h0.64
  text "F26" at 8.019,6.059 h0.64
  text "E26" at 8.019,6.709 h0.64
  text "A16" at 1.519,9.319 h0.64
  text "W15" at 0.869,-2.391 h0.64
  text "K28" at 9.319,3.469 h0.64
  text "B17" at 2.169,8.669 h0.64
  text "Y15" at 0.869,-3.031 h0.64
  text "L27" at 8.669,2.819 h0.64
  text "A17" at 2.169,9.319 h0.64
  text "AC3" at -6.941,-4.981 h0.64
  text "L28" at 9.319,2.819 h0.64
  text "B18" at 2.819,8.669 h0.64
  text "AC2" at -7.591,-4.981 h0.64
  text "M27" at 8.669,2.169 h0.64
  text "B13" at -0.441,8.669 h0.64
  text "M28" at 9.319,2.169 h0.64
  text "A13" at -0.441,9.319 h0.64
  text "N27" at 8.669,1.519 h0.64
  text "Y6" at -5.161,-3.211 h0.64
  text "D17" at 2.169,7.359 h0.64
  text "Y5" at -5.811,-3.211 h0.64
  text "B14" at 0.209,8.669 h0.64
  text "AA3" at -6.941,-3.681 h0.64
  text "H18" at 2.819,4.759 h0.64
  text "AF8" at -3.681,-6.941 h0.64
  text "AA11" at -1.562,-3.502 h0.64
  text "E17" at 2.169,6.709 h0.64
  text "B15" at 0.869,8.669 h0.64
  text "AD8" at -3.681,-5.631 h0.64
  text "A15" at 0.869,9.319 h0.64
  text "AE5" at -5.631,-6.281 h0.64
  text "AE8" at -3.681,-6.281 h0.64
  text "B6" at -5.161,8.489 h0.64
  text "W1" at -8.421,-2.571 h0.64
  text "AG8" at -3.681,-7.591 h0.64
  text "B1" at -8.421,8.489 h0.64
  text "A19" at 3.469,9.319 h0.64
  text "Y4" at -6.461,-3.211 h0.64
  text "F4" at -6.461,5.879 h0.64
  text "B19" at 3.469,8.669 h0.64
  text "Y3" at -7.121,-3.211 h0.64
  text "AG7" at -4.331,-7.591 h0.64
  text "A20" at 4.109,9.319 h0.64
  text "AH6" at -4.981,-8.241 h0.64
  text "H28" at 9.319,4.759 h0.64
  text "B20" at 4.109,8.669 h0.64
  text "AF25" at 7.538,-6.762 h0.64
  text "R2" at -7.771,0.029 h0.64
  text "AE24" at 6.888,-6.102 h0.64
  text "R1" at -8.421,0.029 h0.64
  text "J25" at 7.359,4.109 h0.64
  text "D9" at -3.211,7.179 h0.64
  text "C20" at 4.109,8.019 h0.64
  text "AG28" at 9.498,-7.412 h0.64
  text "AD22" at 5.588,-5.452 h0.64
  text "E23" at 6.059,6.709 h0.64
  text "J24" at 6.709,4.109 h0.64
  text "AC21" at 4.938,-4.802 h0.64
  text "H26" at 8.019,4.759 h0.64
  text "AA2" at -7.591,-3.681 h0.64
  text "AC22" at 5.588,-4.802 h0.64
  text "T2" at -7.771,-0.621 h0.64
  text "J23" at 6.059,4.109 h0.64
  text "AA22" at 5.588,-3.502 h0.64
  text "AH25" at 7.538,-8.062 h0.64
  text "T1" at -8.421,-0.621 h0.64
  text "H27" at 8.669,4.759 h0.64
  text "B7" at -4.511,8.489 h0.64
  text "AF23" at 6.238,-6.762 h0.64
  text "D18" at 2.819,7.359 h0.64
  text "A7" at -4.511,9.139 h0.64
  text "E18" at 2.819,6.709 h0.64
  text "A8" at -3.861,9.139 h0.64
  text "C26" at 8.019,8.019 h0.64
  text "Y1" at -8.421,-3.211 h0.64
  text "R9" at -3.211,0.029 h0.64
  text "U9" at -3.211,-1.271 h0.64
  text "H20" at 4.109,4.759 h0.64
  text "J21" at 4.759,4.109 h0.64
  text "Y2" at -7.771,-3.211 h0.64
  text "L25" at 7.359,2.819 h0.64
  text "W2" at -7.771,-2.571 h0.64
  text "M25" at 7.359,2.169 h0.64
  text "C1" at -8.421,7.839 h0.64
  text "AG6" at -4.981,-7.591 h0.64
  text "A5" at -5.811,9.139 h0.64
  text "AD7" at -4.331,-5.631 h0.64
  text "K27" at 8.669,3.469 h0.64
  text "V7" at -4.511,-1.921 h0.64
  text "D6" at -5.161,7.179 h0.64
  text "AC7" at -4.331,-4.981 h0.64
  text "C2" at -7.771,7.839 h0.64
  text "AC8" at -3.681,-4.981 h0.64
  text "V2" at -7.771,-1.921 h0.64
  text "V12" at -1.091,-1.741 h0.64
  text "V11" at -1.741,-1.741 h0.64
  text "V10" at -2.391,-1.741 h0.64
  text "AH5" at -5.631,-8.241 h0.64
  text "V4" at -6.461,-1.921 h0.64
  text "AG24" at 6.888,-7.412 h0.64
  text "AB20" at 4.288,-4.152 h0.64
  text "V1" at -8.421,-1.921 h0.64
  text "AG26" at 8.198,-7.412 h0.64
  text "C4" at -6.461,7.839 h0.64
  text "B8" at -3.861,8.489 h0.64
  text "A21" at 4.759,9.319 h0.64
  text "U5" at -5.811,-1.271 h0.64
  text "C5" at -5.811,7.839 h0.64
  text "E20" at 4.109,6.709 h0.64
  text "E4" at -6.461,6.529 h0.64
  text "U4" at -6.461,-1.271 h0.64
  text "AG23" at 6.238,-7.412 h0.64
  text "AH27" at 8.848,-8.062 h0.64
  text "N28" at 9.319,1.519 h0.64
  text "AH23" at 6.238,-8.062 h0.64
  text "AE28" at 9.498,-6.102 h0.64
  text "AE27" at 8.848,-6.102 h0.64
  text "AD26" at 8.198,-5.452 h0.64
  text "AC26" at 8.198,-4.802 h0.64
  text "AC25" at 7.538,-4.802 h0.64
  text "AB24" at 6.888,-4.152 h0.64
  text "AA26" at 8.198,-3.502 h0.64
  text "AA24" at 6.888,-3.502 h0.64
  text "AA23" at 6.238,-3.502 h0.64
  text "Y26" at 8.019,-3.031 h0.64
  text "Y24" at 6.709,-3.031 h0.64
  text "Y23" at 6.059,-3.031 h0.64
  text "V20" at 4.109,-1.741 h0.64
  text "V26" at 8.019,-1.741 h0.64
  text "U26" at 8.019,-1.091 h0.64
  text "U23" at 6.059,-1.091 h0.64
  text "V22" at 5.409,-1.741 h0.64
  text "V23" at 6.059,-1.741 h0.64
  text "R23" at 6.059,0.209 h0.64
  text "R26" at 8.019,0.209 h0.64
  text "P26" at 8.019,0.869 h0.64
  text "AB17" at 2.348,-4.152 h0.64
  text "AC18" at 2.998,-4.802 h0.64
  text "Y18" at 2.819,-3.031 h0.64
  text "AF20" at 4.288,-6.762 h0.64
  text "AE20" at 4.288,-6.102 h0.64
  text "AF21" at 4.938,-6.762 h0.64
  text "AE21" at 4.938,-6.102 h0.64
  text "AF26" at 8.198,-6.762 h0.64
  text "AE14" at 0.388,-6.102 h0.64
  text "AC15" at 1.048,-4.802 h0.64
  text "AH18" at 2.998,-8.062 h0.64
  text "AG18" at 2.998,-7.412 h0.64
  text "AF17" at 2.348,-6.762 h0.64
  text "AE17" at 2.348,-6.102 h0.64
  text "AF18" at 2.998,-6.762 h0.64
  text "AH28" at 9.498,-8.062 h0.64
  text "AF15" at 1.048,-6.762 h0.64
  text "AF14" at 0.388,-6.762 h0.64
  text "AH1" at -8.241,-8.241 h0.64
  text "A28" at 9.319,9.319 h0.64
  text "D28" at 9.319,7.359 h0.64
  text "B23" at 6.059,8.669 h0.64
  text "C25" at 7.359,8.019 h0.64
  text "B26" at 8.019,8.669 h0.64
  text "M26" at 8.019,2.169 h0.64
  text "L26" at 8.019,2.819 h0.64
  text "L24" at 6.709,2.819 h0.64
  text "J27" at 8.669,4.109 h0.64
  text "J26" at 8.019,4.109 h0.64
  text "J22" at 5.409,4.109 h0.64
  text "J20" at 4.109,4.109 h0.64
  text "K19" at 3.469,3.469 h0.64
  text "L19" at 3.469,2.819 h0.64
  text "L20" at 4.109,2.819 h0.64
  text "L21" at 4.759,2.819 h0.64
  text "M21" at 4.759,2.169 h0.64
  text "P21" at 4.759,0.869 h0.64
  text "J18" at 2.819,4.109 h0.64
  text "J17" at 2.169,4.109 h0.64
  text "G24" at 6.709,5.409 h0.64
  text "AF3" at -6.941,-6.941 h0.64
  text "AE6" at -4.981,-6.281 h0.64
  text "AF9" at -3.031,-6.941 h0.64
  text "AC9" at -3.031,-4.981 h0.64
  text "AF11" at -1.562,-6.762 h0.64
  text "AC11" at -1.562,-4.802 h0.64
  text "AF12" at -0.912,-6.762 h0.64
  text "AC12" at -0.912,-4.802 h0.64
  text "AD3" at -6.941,-5.631 h0.64
  text "AB6" at -4.981,-4.331 h0.64
  text "AA4" at -6.281,-3.681 h0.64
  text "V8" at -3.861,-1.921 h0.64
  text "U8" at -3.861,-1.271 h0.64
  text "U6" at -5.161,-1.271 h0.64
  text "U7" at -4.511,-1.271 h0.64
  text "AG5" at -5.631,-7.591 h0.64
  text "R3" at -7.121,0.029 h0.64
  text "AB2" at -7.591,-4.331 h0.64
  text "Y11" at -1.741,-3.031 h0.64
  text "AH8" at -3.681,-8.241 h0.64
  text "V3" at -7.121,-1.921 h0.64
  text "T10" at -2.391,-0.441 h0.64
  text "V9" at -3.211,-1.921 h0.64
  text "U10" at -2.391,-1.091 h0.64
  text "Y8" at -3.861,-3.211 h0.64
  text "AB15" at 1.048,-4.152 h0.64
  text "AA14" at 0.388,-3.502 h0.64
  text "AB14" at 0.388,-4.152 h0.64
  text "Y12" at -1.091,-3.031 h0.64
  text "W13" at -0.441,-2.391 h0.64
  text "W12" at -1.091,-2.391 h0.64
  text "AA12" at -0.912,-3.502 h0.64
  text "AB12" at -0.912,-4.152 h0.64
  text "W10" at -2.391,-2.391 h0.64
  text "W11" at -1.741,-2.391 h0.64
  text "AB11" at -1.562,-4.152 h0.64
  text "Y9" at -3.211,-3.211 h0.64
  text "AA9" at -3.031,-3.681 h0.64
  text "G15" at 0.869,5.409 h0.64
  text "F15" at 0.869,6.059 h0.64
  text "L11" at -1.741,2.819 h0.64
  text "M11" at -1.741,2.169 h0.64
  text "N12" at -1.091,1.519 h0.64
  text "N11" at -1.741,1.519 h0.64
  text "P12" at -1.091,0.869 h0.64
  text "P14" at 0.209,0.869 h0.64
  text "R10" at -2.391,0.209 h0.64
  text "R11" at -1.741,0.209 h0.64
  text "T11" at -1.741,-0.441 h0.64
  text "U17" at 2.169,-1.091 h0.64
  text "W17" at 2.169,-2.391 h0.64
  text "AA17" at 2.348,-3.502 h0.64
  text "U16" at 1.519,-1.091 h0.64
  text "V16" at 1.519,-1.741 h0.64
  text "R15" at 0.869,0.209 h0.64
  text "T15" at 0.869,-0.441 h0.64
  text "U15" at 0.869,-1.091 h0.64
  text "V15" at 0.869,-1.741 h0.64
  text "AA15" at 1.048,-3.502 h0.64
  text "V13" at -0.441,-1.741 h0.64
  text "U14" at 0.209,-1.091 h0.64
  text "T14" at 0.209,-0.441 h0.64
  text "R14" at 0.209,0.209 h0.64
  text "V14" at 0.209,-1.741 h0.64
  text "M18" at 2.819,2.169 h0.64
  text "N17" at 2.169,1.519 h0.64
  text "P15" at 0.869,0.869 h0.64
  text "N18" at 2.819,1.519 h0.64
  text "P17" at 2.169,0.869 h0.64
  text "R17" at 2.169,0.209 h0.64
  text "R18" at 2.819,0.209 h0.64
  text "R19" at 3.469,0.209 h0.64
  text "T17" at 2.169,-0.441 h0.64
  text "T18" at 2.819,-0.441 h0.64
  text "T19" at 3.469,-0.441 h0.64
  text "U18" at 2.819,-1.091 h0.64
  text "M16" at 1.519,2.169 h0.64
  text "N15" at 0.869,1.519 h0.64
  text "K14" at 0.209,3.469 h0.64
  text "L14" at 0.209,2.819 h0.64
  text "L13" at -0.441,2.819 h0.64
  text "M14" at 0.209,2.169 h0.64
  text "M13" at -0.441,2.169 h0.64
  text "N14" at 0.209,1.519 h0.64
  text "K13" at -0.441,3.469 h0.64
  text "K12" at -1.091,3.469 h0.64
  text "K11" at -1.741,3.469 h0.64
  text "P3" at -7.121,0.689 h0.64
  text "N1" at -8.421,1.339 h0.64
  text "R6" at -5.161,0.029 h0.64
  text "P6" at -5.161,0.689 h0.64
  text "L8" at -3.861,2.639 h0.64
  text "M8" at -3.861,1.989 h0.64
  text "M6" at -5.161,1.989 h0.64
  text "L5" at -5.811,2.639 h0.64
  text "J8" at -3.861,3.929 h0.64
  text "H6" at -5.161,4.579 h0.64
  text "G6" at -5.161,5.229 h0.64
  text "G8" at -3.861,5.229 h0.64
  text "G9" at -3.211,5.229 h0.64
  text "F9" at -3.211,5.879 h0.64
  text "E7" at -4.511,6.529 h0.64
  text "J5" at -5.811,3.929 h0.64
  text "M2" at -7.771,1.989 h0.64
  text "M3" at -7.121,1.989 h0.64
  text "L3" at -7.121,2.639 h0.64
  text "K1" at -8.421,3.289 h0.64
  text "A18" at 2.819,9.319 h0.64
  text "G5" at -5.811,5.229 h0.64
  text "J3" at -7.121,3.929 h0.64
  text "H3" at -7.121,4.579 h0.64
  text "H2" at -7.771,4.579 h0.64
  text "F3" at -7.121,5.879 h0.64
  text "F1" at -8.421,5.879 h0.64
  text "E3" at -7.121,6.529 h0.64
  text "D2" at -7.771,7.179 h0.64
  text "D3" at -7.121,7.179 h0.64
  text "C3" at -7.121,7.839 h0.64
  text "A1" at -8.421,9.139 h0.64
  text "A3" at -7.121,9.139 h0.64
  text "B5" at -5.811,8.489 h0.64
  text "C6" at -5.161,7.839 h0.64
  text "C8" at -3.861,7.839 h0.64
  text "C9" at -3.211,7.839 h0.64
  text "A6" at -5.161,9.139 h0.64
  text "B9" at -3.211,8.489 h0.64
  text "A10" at -2.391,9.319 h0.64
  text "F12" at -1.091,6.059 h0.64
  text "G11" at -1.741,5.409 h0.64
  text "F14" at 0.209,6.059 h0.64
  text "G14" at 0.209,5.409 h0.64
  text "G18" at 2.819,5.409 h0.64
  text "F17" at 2.169,6.059 h0.64
  text "G17" at 2.169,5.409 h0.64
  text "C14" at 0.209,8.019 h0.64
  text "C15" at 0.869,8.019 h0.64
  text "D11" at -1.741,7.359 h0.64
  text "B12" at -1.091,8.669 h0.64
  text "A14" at 0.209,9.319 h0.64
  text "B16" at 1.519,8.669 h0.64
  text "C17" at 2.169,8.019 h0.64
  text "C18" at 2.819,8.019 h0.64
  text "C11" at -1.741,8.019 h0.64
  text "C12" at -1.091,8.019 h0.64
  text "G12" at -1.091,5.409 h0.64
  text "U1" at -8.421,-1.271 h0.64
  text "H22" at 5.409,4.759 h0.64
  text "N10" at -2.391,1.519 h0.64
  text "U22" at 5.409,-1.091 h0.64
  text "R22" at 5.409,0.209 h0.64
  text "AH7" at -4.331,-8.241 h0.64
  text "AG22" at 5.588,-7.412 h0.64
  text "AH22" at 5.588,-8.062 h0.64
  text "AA28" at 9.498,-3.502 h0.64
  text "P16" at 1.519,0.869 h0.64
  text "R16" at 1.519,0.209 h0.64
  text "N16" at 1.519,1.519 h0.64
  text "T16" at 1.519,-0.441 h0.64
  text "P13" at -0.441,0.869 h0.64
  text "N13" at -0.441,1.519 h0.64
  text "L12" at -1.091,2.819 h0.64
  text "M12" at -1.091,2.169 h0.64
  text "T12" at -1.091,-0.441 h0.64
  text "R12" at -1.091,0.209 h0.64
  text "AD20" at 4.288,-5.452 h0.64
  text "AG21" at 4.938,-7.412 h0.64
  text "AA27" at 8.848,-3.502 h0.64
  text "R13" at -0.441,0.209 h0.64
  text "U13" at -0.441,-1.091 h0.64
  text "U11" at -1.741,-1.091 h0.64
  text "U12" at -1.091,-1.091 h0.64
  text "T13" at -0.441,-0.441 h0.64
  text "AH21" at 4.938,-8.062 h0.64
  text "D5" at -5.811,7.179 h0.64
  text "N19" at 3.469,1.519 h0.64
  text "P20" at 4.109,0.869 h0.64
  text "P18" at 2.819,0.869 h0.64
  text "P19" at 3.469,0.869 h0.64
  text "M19" at 3.469,2.169 h0.64
  text "AG20" at 4.288,-7.412 h0.64
  text "U2" at -7.771,-1.271 h0.64
  text "E6" at -5.161,6.529 h0.64
  text "AH2" at -7.591,-8.241 h0.64
  text "AH20" at 4.288,-8.062 h0.64
  text "G21" at 4.759,5.409 h0.64
  text "E11" at -1.741,6.709 h0.64
  text "M22" at 5.409,2.169 h0.64
  text "W18" at 2.819,-2.391 h0.64
  text "AE2" at -7.591,-6.281 h0.64
  text "AH19" at 3.648,-8.062 h0.64
  text "F22" at 5.409,6.059 h0.64
  text "E9" at -3.211,6.529 h0.64
  text "Y21" at 4.759,-3.031 h0.64
  text "AA5" at -5.631,-3.681 h0.64
  text "AG19" at 3.648,-7.412 h0.64
  text "G20" at 4.109,5.409 h0.64
  text "AB28" at 9.498,-4.152 h0.64
  text "Y20" at 4.109,-3.031 h0.64
  text "W19" at 3.469,-2.391 h0.64
  text "AB8" at -3.681,-4.331 h0.64
  text "F21" at 4.759,6.059 h0.64
  text "AB27" at 8.848,-4.152 h0.64
  text "L22" at 5.409,2.819 h0.64
  text "AE3" at -6.941,-6.281 h0.64
  text "AH16" at 1.698,-8.062 h0.64
  text "B3" at -7.121,8.489 h0.64
  text "H17" at 2.169,4.759 h0.64
  text "AA7" at -4.331,-3.681 h0.64
  text "AH17" at 2.348,-8.062 h0.64
  text "V21" at 4.759,-1.741 h0.64
  text "V19" at 3.469,-1.741 h0.64
  text "AC4" at -6.281,-4.981 h0.64
  text "AG16" at 1.698,-7.412 h0.64
  text "R21" at 4.759,0.209 h0.64
  text "R20" at 4.109,0.209 h0.64
  text "U20" at 4.109,-1.091 h0.64
  text "U21" at 4.759,-1.091 h0.64
  text "P11" at -1.741,0.869 h0.64
  text "AD1" at -8.241,-5.631 h0.64
  text "AG17" at 2.348,-7.412 h0.64
  text "M20" at 4.109,2.169 h0.64
  text "V17" at 2.169,-1.741 h0.64
  text "V18" at 2.819,-1.741 h0.64
  text "AA1" at -8.241,-3.681 h0.64
  text "AH4" at -6.281,-8.241 h0.64
  text "B4" at -6.461,8.489 h0.64
  text "B21" at 4.759,8.669 h0.64
  text "AC28" at 9.498,-4.802 h0.64
  text "A4" at -6.461,9.139 h0.64
  text "AC27" at 8.848,-4.802 h0.64
  text "AG15" at 1.048,-7.412 h0.64
  text "AD28" at 9.498,-5.452 h0.64
  text "AH15" at 1.048,-8.062 h0.64
  text "AD27" at 8.848,-5.452 h0.64
  text "Y25" at 7.359,-3.031 h0.64
  text "AG25" at 7.538,-7.412 h0.64
  text "AA25" at 7.538,-3.502 h0.64
  text "AG2" at -7.591,-7.591 h0.64
  text "AB9" at -3.031,-4.331 h0.64
  text "A2" at -7.771,9.139 h0.64
  text "U19" at 3.469,-1.091 h0.64
  text "B2" at -7.771,8.489 h0.64
  text "E8" at -3.861,6.529 h0.64
  text "AH13" at -0.262,-8.062 h0.64
  text "D8" at -3.861,7.179 h0.64
  text "AH14" at 0.388,-8.062 h0.64
  text "AG14" at 0.388,-7.412 h0.64
  text "A24" at 6.709,9.319 h0.64
  text "AG13" at -0.262,-7.412 h0.64
  text "F11" at -1.741,6.059 h0.64
  text "AD21" at 4.938,-5.452 h0.64
  text "C21" at 4.759,8.019 h0.64
  text "B24" at 6.709,8.669 h0.64
  text "H7" at -4.511,4.579 h0.64
  text "AE23" at 6.238,-6.102 h0.64
  text "AB18" at 2.998,-4.152 h0.64
  text "D21" at 4.759,7.359 h0.64
  text "H14" at 0.209,4.759 h0.64
  text "H15" at 0.869,4.759 h0.64
  text "L9" at -3.211,2.639 h0.64
  text "H11" at -1.741,4.759 h0.64
  text "H12" at -1.091,4.759 h0.64
  text "H9" at -3.211,4.579 h0.64
  text "J9" at -3.211,3.929 h0.64
  text "M9" at -3.211,1.989 h0.64
  text "A25" at 7.359,9.319 h0.64
  text "E21" at 4.759,6.709 h0.64
  text "E22" at 5.409,6.709 h0.64
  text "AA18" at 2.998,-3.502 h0.64
  text "B25" at 7.359,8.669 h0.64
  text "B22" at 5.409,8.669 h0.64
  text "A26" at 8.019,9.319 h0.64
  text "AD23" at 6.238,-5.452 h0.64
  text "AG27" at 8.848,-7.412 h0.64
  text "U3" at -7.121,-1.271 h0.64
  text "G23" at 6.059,5.409 h0.64
3D body: height 3.81, standoff 0, extent -10.5,-10.5 10.5,10.5

## C0201 [mm] "C0201"
pads (2):
  rect 0.35x0.35 smd: 1(-0.275,0) 2(0.275,0)
Top Overlay:
  lines w0.102: -0.508,-0.254 -0.508,0.254 0.508,0.254 0.508,-0.254 -0.508,-0.254
  text "4.7uF" at -0.431,-0.583 h0.3
Top 3D Body:
  region: -0.475,-0.175 -0.475,0.175 0.475,0.175 0.475,-0.175
Mechanical 12:
  text "1" at -0.491,-0.216 h0.76
  text "2" at 0.06,-0.216 h0.76
Top Assembly:
  lines w0.025: -0.55,-0.3 0.55,-0.3 0.55,0.3 -0.55,0.3 -0.55,-0.3 ; -0.475,-0.175 0.475,-0.175 0.475,0.175 -0.475,0.175 -0.475,-0.175
  text "4.7uF" at 0.762,-0.254 h0.76
  text ".Designator" at -0.647,-1.028 h0.76
3D body: height 3.81, standoff 0, extent -0.475,-0.175 0.475,0.175

## C0402 [mm] "C0402"
pads (2):
  rect 0.599x0.599 smd: 1(0.5,0) 2(-0.5,0)
Top Overlay:
  lines w0.102: -0.94,-0.432 -0.94,0.432 0.94,0.432 0.94,-0.432 -0.94,-0.432
  text "10uF" at -0.488,0.152 h0.3
Top 3D Body:
  region: -0.94,-0.432 -0.94,0.432 0.94,0.432 0.94,-0.432
Mechanical 12:
  text "2" at -0.754,0 h0.64
  text "1" at 0.246,0 h0.64
Top Assembly:
  dashed: 0.94,0.432 0.94,-0.432 -0.94,-0.432 -0.94,0.432
3D body: height 3.81, standoff 0, extent -0.94,-0.432 0.94,0.432

## C0603 [mil] "C0603"
pads (2):
  rect 31.5x31.5 smd: 1(-31.5,0) 2(31.5,0)
Top Overlay:
  lines w5: -10,-25 -55,-25 -55,25 -10,25 ; 10,-25 55,-25 55,25 10,25
  text "22uF" at -19.2,6 h12
Top 3D Body:
  region: -48,16 48,16 48,-16 -48,-16
Mechanical 12:
  text "1" at -49.5,0 h45
  text "2" at 13.5,0 h45
Top Assembly:
  text "C0603" at -117,37 h35
3D body: height 150, standoff 0, extent -48,-16 48,16

## C0805 [mm] "C0805"
pads (2):
  rect 1.16x1.47 smd: 1(-0.89,0) 2(0.89,0)
Top Overlay:
  lines w0.2: -0.45,-1.035 -1.37,-1.035 cw(c-1.37,-0.635) -1.77,-0.635 -1.77,0.635 cw(c-1.37,0.635) -1.37,1.035 -0.45,1.035 ; 0.45,-1.035 1.37,-1.035 ccw(c1.37,-0.635) 1.77,-0.635 1.77,0.635 ccw(c1.37,0.635) 1.37,1.035 0.45,1.035
  text "47uF" at 0,0.64 h0.3
Top 3D Body:
  region: -1.47,-0.735 -1.47,0.735 1.47,0.735 1.47,-0.735
Mechanical 12:
  text "1" at -0.89,0.315 h0.79
  text "2" at 0.89,0.315 h0.79
3D body: height 3.81, standoff 0, extent -1.47,-0.735 1.47,0.735

## CSP20_1R96X1R56X0R66 [mm] "CSP20_1R96X1R56X0R66"
pads (20):
  round 0.24 smd: A1(-0.6,0.8) A2(-0.2,0.8) A3(0.2,0.8) A4(0.6,0.8) B1(-0.6,0.4) B2(-0.2,0.4) B3(0.2,0.4) B4(0.6,0.4) C1(-0.6,0) C2(-0.2,0) C3(0.2,0) C4(0.6,0) D1(-0.6,-0.4) D2(-0.2,-0.4) D3(0.2,-0.4) D4(0.6,-0.4) E1(-0.6,-0.8) E2(-0.2,-0.8) E3(0.2,-0.8) E4(0.6,-0.8)
Top Overlay:
  dashed: -0.93,1.524 -0.95,1.622 -1.005,1.704 -1.088,1.759 -1.185,1.779 -1.283,1.759 -1.31,1.741 -1.365,1.704 -1.421,1.622 -1.44,1.524 -1.421,1.426 -1.365,1.344 -1.31,1.307 -1.283,1.289 -1.185,1.269 -1.088,1.289 -1.005,1.344 -0.95,1.426
  lines w0.1: -1.28,-1.009 -1.28,-1.48 -0.989,-1.48 ; -1.28,-0.685 -1.28,0.062 ; -1.28,0.43 -1.28,0.9 ; -0.671,-1.48 -0.353,-1.48 ; -0.353,1.48 -0.7,1.48 -1.28,0.9 ; -0.048,-1.48 0.569,-1.48 ; -0.048,1.48 0.569,1.48 ; 0.893,-1.48 1.28,-1.48 1.28,-1.009 ; 0.893,1.48 1.28,1.48 1.28,1.146 ; 1.28,-0.685 1.28,0.062 ; 1.28,0.43 1.28,0.816 ; -1.28,0.9 -1.28,0.9
  text "TCS4525" at -0.853,-0.152 h0.3
Top 3D Body:
  region: -1.3,1.5 -1.3,-1.5 1.3,-1.5 1.3,1.5
  region: -0.766,1 -0.766,-1 0.8,-1 0.8,1
Mechanical 12:
  text "A1" at -0.803,0.8 h0.25
  text "B1" at -0.803,0.4 h0.25
  text "A3" at -0.003,0.8 h0.25
  text "A2" at -0.403,0.8 h0.25
  text "A4" at 0.397,0.8 h0.25
  text "E2" at -0.403,-0.8 h0.25
  text "E1" at -0.803,-0.8 h0.25
  text "D2" at -0.403,-0.4 h0.25
  text "D1" at -0.803,-0.4 h0.25
  text "B2" at -0.403,0.4 h0.25
  text "B3" at -0.003,0.4 h0.25
  text "B4" at 0.397,0.4 h0.25
  text "C1" at -0.803,0 h0.25
  text "C2" at -0.403,0 h0.25
  text "C3" at -0.003,0 h0.25
  text "C4" at 0.397,0 h0.25
  text "D3" at -0.003,-0.4 h0.25
  text "D4" at 0.397,-0.4 h0.25
  text "E3" at -0.003,-0.8 h0.25
  text "E4" at 0.397,-0.8 h0.25
3D body: height 3.81, standoff 0, extent -1.3,-1.5 1.3,1.5
3D body: height 3.81, standoff 0, extent -0.766,-1 0.8,1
